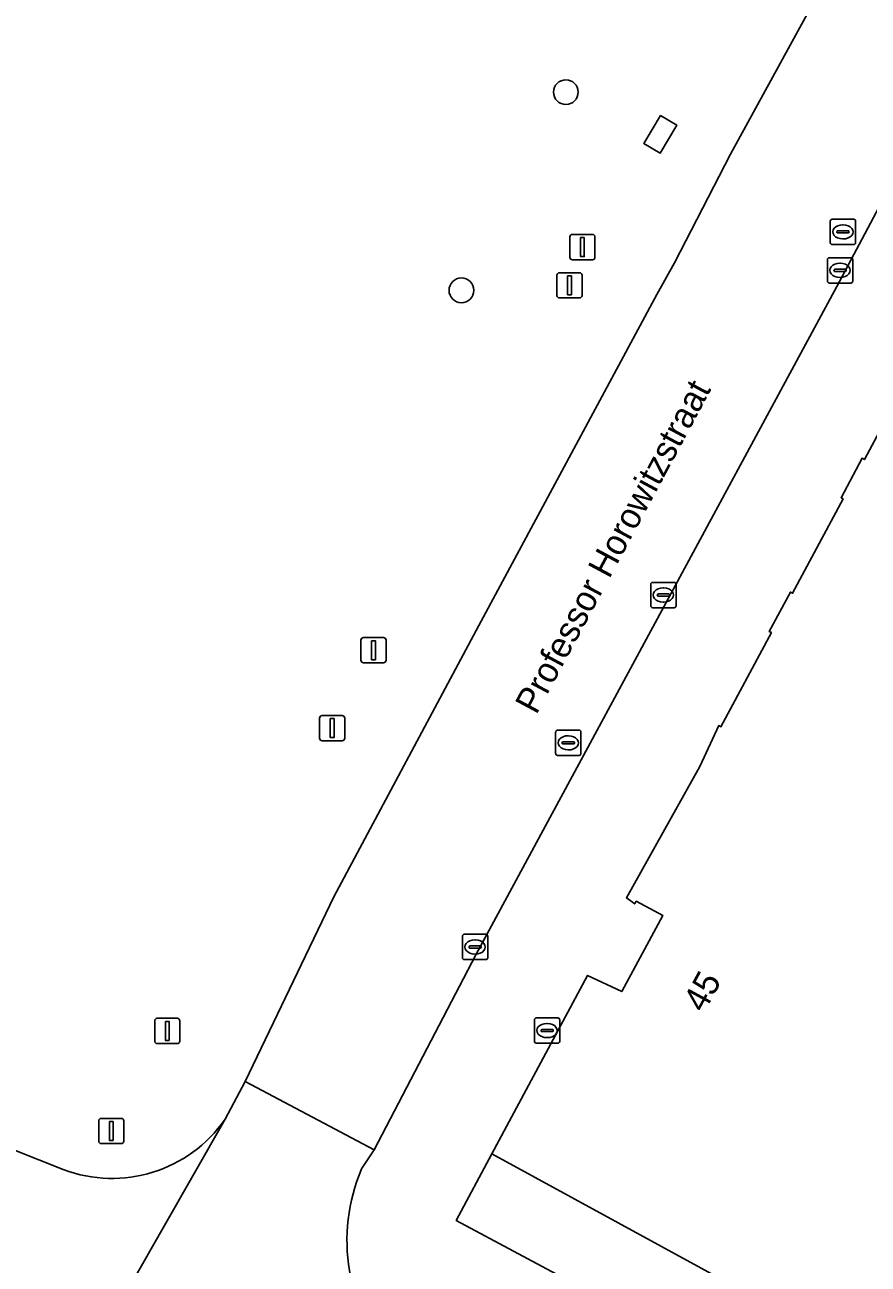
# Model space of a CAD drawing. Extents: x 159489 to 160304, y 383825 to 384531.
# Drawn here: x 159958.75 to 159992.1, y 384044.23 to 384093.22 of the extents above; entities that cross this region are included whole.
import ezdxf

# ---------------------------------------------------------------- set-up
doc = ezdxf.new("R2010")
doc.units = 0
for name, color, linetype in [('IMGEO_Boom', 7, 'Continuous'), ('IMGEO_Groenvoorziening', 7, 'Continuous'), ('IMGEO_Kolk', 7, 'Continuous'), ('IMGEO_Lichtmast', 7, 'Continuous'), ('IMGEO_Openbare_ruimte_label', 7, 'Continuous'), ('IMGEO_Pand', 7, 'Continuous'), ('IMGEO_Pand_nummerreeks', 7, 'Continuous'), ('IMGEO_Rijbaan_lokaal_gesloten', 7, 'Continuous'), ('IMGEO_Rioolput', 7, 'Continuous'), ('IMGEO_Terreindeel_open', 7, 'Continuous'), ('IMGEO_Voetpad_open', 7, 'Continuous')]:
    doc.layers.add(name, color=color, linetype=linetype)

msp = doc.modelspace()

# ---------------------------------------------------------------- linework, layer by layer
at = {"layer": 'IMGEO_Boom'}
for centre in [(159980.146, 384090.56), (159976.018, 384082.727)]:
    msp.add_circle(centre, 0.489, dxfattribs=at)
at = {"layer": 'IMGEO_Groenvoorziening'}
for points in [[(159941.364, 384123.56), (159925.758, 384094.623), (159925.487, 384093.814), (159920.135, 384063.9), (159960.274, 384047.972)], [(159966.672, 384049.958), (159967.463, 384051.458), (159970.972, 384058.755), (159976.703, 384069.478), (159983.744, 384082.565), (159984.446, 384083.814), (159986.651, 384088.113), (159991.605, 384097.15)]]:
    msp.add_lwpolyline(points, dxfattribs=at)
msp.add_lwpolyline([(159983.89, 384089.636), (159984.532, 384089.252), (159983.871, 384088.147), (159983.229, 384088.531)], close=True, dxfattribs=at)
msp.add_arc((159962.194, 384053.086), 5.462, 249.4231, 325.0666, dxfattribs=at)
at = {"layer": 'IMGEO_Kolk'}
for p, q in [((159990.489, 384083.089), (159990.489, 384083.941)), ((159990.564, 384084.015), (159991.416, 384084.015)), ((159991.49, 384083.941), (159991.49, 384083.089)), ((159990.748, 384083.509), (159990.748, 384083.521)), ((159991.186, 384083.472), (159990.788, 384083.472)), ((159990.791, 384083.558), (159991.189, 384083.558)), ((159990.977, 384083.795), (159991.002, 384083.795)), ((159991.232, 384083.521), (159991.232, 384083.509)), ((159991.416, 384083.015), (159990.564, 384083.015)), ((159991, 384083.235), (159990.975, 384083.235)), ((159983.579, 384071.182), (159984.431, 384071.182)), ((159983.504, 384070.256), (159983.504, 384071.108)), ((159983.763, 384070.676), (159983.763, 384070.688)), ((159983.806, 384070.725), (159984.204, 384070.725)), ((159983.992, 384070.962), (159984.017, 384070.962)), ((159984.247, 384070.688), (159984.247, 384070.676)), ((159984.505, 384071.108), (159984.505, 384070.256)), ((159984.431, 384070.182), (159983.579, 384070.182)), ((159984.201, 384070.639), (159983.803, 384070.639)), ((159984.015, 384070.402), (159983.99, 384070.402)), ((159976.058, 384056.345), (159976.058, 384057.197)), ((159976.133, 384057.271), (159976.985, 384057.271)), ((159976.546, 384057.051), (159976.571, 384057.051)), ((159977.059, 384057.197), (159977.059, 384056.345)), ((159976.317, 384056.765), (159976.317, 384056.777)), ((159976.755, 384056.728), (159976.357, 384056.728)), ((159976.36, 384056.814), (159976.758, 384056.814)), ((159976.569, 384056.491), (159976.544, 384056.491)), ((159976.801, 384056.777), (159976.801, 384056.765)), ((159976.985, 384056.271), (159976.133, 384056.271))]:
    msp.add_line(p, q, dxfattribs=at)
for points in [[(159990.489, 384083.089), (159990.489, 384083.941)], [(159990.564, 384084.015), (159991.416, 384084.015)], [(159991.49, 384083.941), (159991.49, 384083.089)], [(159991.416, 384083.015), (159990.564, 384083.015)], [(159983.579, 384071.182), (159984.431, 384071.182)], [(159983.504, 384070.256), (159983.504, 384071.108)], [(159984.505, 384071.108), (159984.505, 384070.256)], [(159984.431, 384070.182), (159983.579, 384070.182)], [(159976.058, 384056.345), (159976.058, 384057.197)], [(159976.133, 384057.271), (159976.985, 384057.271)], [(159977.059, 384057.197), (159977.059, 384056.345)], [(159976.985, 384056.271), (159976.133, 384056.271)]]:
    msp.add_lwpolyline(points, dxfattribs=at)
for centre, radius, start, end in [((159990.566, 384083.939), 0.0765, 91.552, 178.448), ((159990.566, 384083.939), 0.0765, 91.552, 178.448), ((159991.414, 384083.939), 0.0765, 1.552, 88.448), ((159991.414, 384083.939), 0.0765, 1.552, 88.448), ((159990.788, 384083.518), 0.0403, 85.8775, 175.7526), ((159990.785, 384083.508), 0.0366, 178.938, 274.7102), ((159991.189, 384083.515), 0.043, 264.8664, 352.4533), ((159991.193, 384083.52), 0.0386, 1.7309, 96.639), ((159990.566, 384083.091), 0.0765, 181.552, 268.448), ((159990.566, 384083.091), 0.0765, 181.552, 268.448), ((159991.414, 384083.091), 0.0765, 271.552, 358.448), ((159991.414, 384083.091), 0.0765, 271.552, 358.448), ((159983.581, 384071.106), 0.0765, 91.552, 178.448), ((159983.581, 384071.106), 0.0765, 91.552, 178.448), ((159984.429, 384071.106), 0.0765, 1.552, 88.448), ((159984.429, 384071.106), 0.0765, 1.552, 88.448), ((159983.803, 384070.685), 0.0403, 85.8775, 175.7526), ((159983.8, 384070.675), 0.0366, 178.938, 274.7102), ((159984.204, 384070.682), 0.043, 264.8664, 352.4533), ((159984.208, 384070.687), 0.0386, 1.7309, 96.639), ((159983.581, 384070.258), 0.0765, 181.552, 268.448), ((159983.581, 384070.258), 0.0765, 181.552, 268.448), ((159984.429, 384070.258), 0.0765, 271.552, 358.448), ((159984.429, 384070.258), 0.0765, 271.552, 358.448), ((159976.135, 384057.195), 0.0765, 91.552, 178.448), ((159976.135, 384057.195), 0.0765, 91.552, 178.448), ((159976.983, 384057.195), 0.0765, 1.552, 88.448), ((159976.983, 384057.195), 0.0765, 1.552, 88.448), ((159976.357, 384056.774), 0.0403, 85.8775, 175.7526), ((159976.354, 384056.764), 0.0366, 178.938, 274.7102), ((159976.758, 384056.771), 0.043, 264.8664, 352.4533), ((159976.762, 384056.776), 0.0386, 1.7309, 96.639), ((159976.135, 384056.347), 0.0765, 181.552, 268.448), ((159976.135, 384056.347), 0.0765, 181.552, 268.448), ((159976.983, 384056.347), 0.0765, 271.552, 358.448), ((159976.983, 384056.347), 0.0765, 271.552, 358.448)]:
    msp.add_arc(centre, radius, start, end, dxfattribs=at)
for centre, major_axis, ratio, start_param, end_param in [((159990.976, 384083.515), (-0.387, 0.002), 0.722429, 4.712389, 7.853982), ((159991.001, 384083.515), (-0.39, 0.002), 0.717154, 1.570796, 4.712389), ((159983.991, 384070.682), (-0.387, 0.002), 0.722429, 4.712389, 7.853982), ((159984.016, 384070.682), (-0.39, 0.002), 0.717154, 1.570796, 4.712389), ((159976.545, 384056.771), (-0.387, 0.002), 0.722429, 4.712389, 7.853982), ((159976.57, 384056.771), (-0.39, 0.002), 0.717154, 1.570796, 4.712389)]:
    msp.add_ellipse(centre, major_axis=major_axis, ratio=ratio, start_param=start_param, end_param=end_param, dxfattribs=at)
at = {"layer": 'IMGEO_Lichtmast'}
for p, q in [((159980.406, 384084.935), (159981.196, 384084.935)), ((159981.196, 384084.935), (159980.406, 384084.935)), ((159980.306, 384084.035), (159980.306, 384084.835)), ((159980.306, 384084.835), (159980.306, 384084.035)), ((159981.296, 384084.835), (159981.296, 384084.035)), ((159981.296, 384084.035), (159981.296, 384084.835)), ((159981.196, 384083.935), (159980.406, 384083.935)), ((159980.406, 384083.935), (159981.196, 384083.935)), ((159979.896, 384083.424), (159980.686, 384083.424)), ((159980.686, 384083.424), (159979.896, 384083.424)), ((159979.796, 384082.524), (159979.796, 384083.324)), ((159979.796, 384083.324), (159979.796, 384082.524)), ((159980.786, 384083.324), (159980.786, 384082.524)), ((159980.786, 384082.524), (159980.786, 384083.324)), ((159980.686, 384082.424), (159979.896, 384082.424)), ((159979.896, 384082.424), (159980.686, 384082.424)), ((159972.046, 384068.102), (159972.046, 384068.902)), ((159972.046, 384068.902), (159972.046, 384068.102)), ((159972.146, 384069.002), (159972.936, 384069.002)), ((159972.936, 384069.002), (159972.146, 384069.002)), ((159973.036, 384068.902), (159973.036, 384068.102)), ((159973.036, 384068.102), (159973.036, 384068.902)), ((159972.936, 384068.002), (159972.146, 384068.002)), ((159972.146, 384068.002), (159972.936, 384068.002)), ((159970.412, 384065.021), (159970.412, 384065.821)), ((159970.412, 384065.821), (159970.412, 384065.021)), ((159970.512, 384065.921), (159971.302, 384065.921)), ((159971.302, 384065.921), (159970.512, 384065.921)), ((159971.402, 384065.821), (159971.402, 384065.021)), ((159971.402, 384065.021), (159971.402, 384065.821)), ((159971.302, 384064.921), (159970.512, 384064.921)), ((159970.512, 384064.921), (159971.302, 384064.921)), ((159963.891, 384053.051), (159963.891, 384053.851)), ((159963.891, 384053.851), (159963.891, 384053.051)), ((159963.991, 384053.951), (159964.781, 384053.951)), ((159964.781, 384053.951), (159963.991, 384053.951)), ((159964.881, 384053.851), (159964.881, 384053.051)), ((159964.881, 384053.051), (159964.881, 384053.851)), ((159964.781, 384052.951), (159963.991, 384052.951)), ((159963.991, 384052.951), (159964.781, 384052.951)), ((159961.676, 384049.097), (159961.676, 384049.897)), ((159961.676, 384049.897), (159961.676, 384049.097)), ((159961.776, 384049.997), (159962.566, 384049.997)), ((159962.566, 384049.997), (159961.776, 384049.997)), ((159962.666, 384049.897), (159962.666, 384049.097)), ((159962.666, 384049.097), (159962.666, 384049.897)), ((159962.566, 384048.997), (159961.776, 384048.997)), ((159961.776, 384048.997), (159962.566, 384048.997))]:
    msp.add_line(p, q, dxfattribs=at)
for points in [[(159980.726, 384084.81), (159980.876, 384084.81), (159980.876, 384084.06), (159980.726, 384084.06), (159980.726, 384084.81)], [(159980.216, 384083.299), (159980.366, 384083.299), (159980.366, 384082.549), (159980.216, 384082.549), (159980.216, 384083.299)], [(159972.466, 384068.877), (159972.616, 384068.877), (159972.616, 384068.127), (159972.466, 384068.127), (159972.466, 384068.877)], [(159970.832, 384065.796), (159970.982, 384065.796), (159970.982, 384065.046), (159970.832, 384065.046), (159970.832, 384065.796)], [(159964.311, 384053.826), (159964.461, 384053.826), (159964.461, 384053.076), (159964.311, 384053.076), (159964.311, 384053.826)], [(159962.096, 384049.872), (159962.246, 384049.872), (159962.246, 384049.122), (159962.096, 384049.122), (159962.096, 384049.872)]]:
    msp.add_lwpolyline(points, dxfattribs=at)
for centre, start, end in [((159980.406, 384084.835), 90, 180), ((159980.406, 384084.835), 90, 180), ((159981.196, 384084.835), 0, 90), ((159981.196, 384084.835), 360, 90), ((159980.406, 384084.035), 180, 270), ((159980.406, 384084.035), 180, 270), ((159981.196, 384084.035), 270, 0), ((159981.196, 384084.035), 270, 0), ((159979.896, 384083.324), 90, 180), ((159979.896, 384083.324), 90, 180), ((159980.686, 384083.324), 0, 90), ((159980.686, 384083.324), 360, 90), ((159979.896, 384082.524), 180, 270), ((159979.896, 384082.524), 180, 270), ((159980.686, 384082.524), 270, 0), ((159980.686, 384082.524), 270, 0), ((159972.146, 384068.902), 90, 180), ((159972.146, 384068.902), 90, 180), ((159972.936, 384068.902), 0, 90), ((159972.936, 384068.902), 360, 90), ((159972.146, 384068.102), 180, 270), ((159972.146, 384068.102), 180, 270), ((159972.936, 384068.102), 270, 0), ((159972.936, 384068.102), 270, 0), ((159970.512, 384065.821), 90, 180), ((159970.512, 384065.821), 90, 180), ((159971.302, 384065.821), 0, 90), ((159971.302, 384065.821), 360, 90), ((159970.512, 384065.021), 180, 270), ((159970.512, 384065.021), 180, 270), ((159971.302, 384065.021), 270, 0), ((159971.302, 384065.021), 270, 0), ((159963.991, 384053.851), 90, 180), ((159963.991, 384053.851), 90, 180), ((159964.781, 384053.851), 0, 90), ((159964.781, 384053.851), 360, 90), ((159963.991, 384053.051), 180, 270), ((159963.991, 384053.051), 180, 270), ((159964.781, 384053.051), 270, 0), ((159964.781, 384053.051), 270, 0), ((159961.776, 384049.897), 90, 180), ((159961.776, 384049.897), 90, 180), ((159962.566, 384049.897), 0, 90), ((159962.566, 384049.897), 360, 90), ((159961.776, 384049.097), 180, 270), ((159961.776, 384049.097), 180, 270), ((159962.566, 384049.097), 270, 0), ((159962.566, 384049.097), 270, 0)]:
    msp.add_arc(centre, 0.1, start, end, dxfattribs=at)
at = {"layer": 'IMGEO_Pand'}
msp.add_lwpolyline([(159993.956, 384079.778), (159991.95, 384076.039), (159991.862, 384076.087), (159991.026, 384074.53), (159991.114, 384074.482), (159989.113, 384070.75), (159989.025, 384070.798), (159988.184, 384069.244), (159988.272, 384069.196), (159986.28, 384065.474), (159986.191, 384065.521), (159985.447, 384063.909), (159982.545, 384058.712), (159982.871, 384058.474), (159982.928, 384058.58), (159983.985, 384058.011), (159982.353, 384055.006), (159981.007, 384055.649), (159977.223, 384048.598), (159987.204, 384043.143), (159988.813, 384042.4), (159992.053, 384040.657), (159992.006, 384040.568), (159993.634, 384039.812)], dxfattribs=at)
at = {"layer": 'IMGEO_Rijbaan_lokaal_gesloten'}
for points in [[(159994.225, 384101.931), (159994.034, 384101.581), (159993.886, 384101.31), (159993.361, 384100.352), (159991.945, 384097.77), (159991.605, 384097.15), (159986.651, 384088.113), (159984.446, 384083.814), (159983.744, 384082.565), (159976.703, 384069.478), (159970.972, 384058.755), (159967.463, 384051.458), (159972.563, 384048.752), (159976.592, 384056.454), (159990.865, 384082.876)], [(159990.865, 384082.876), (159999.091, 384098.355), (159999.262, 384098.753)], [(159960.274, 384047.972), (159920.135, 384063.9)], [(159972.072, 384047.997), (159972.563, 384048.752), (159967.463, 384051.458), (159966.672, 384049.958), (159959.376, 384037.169)], [(159959.376, 384037.169), (159966.672, 384049.958)]]:
    msp.add_lwpolyline(points, dxfattribs=at)
for centre, radius, start, end in [((159962.194, 384053.086), 5.462, 249.4231, 325.0666), ((159978.703, 384045.162), 7.212, 156.8492, 222.0391)]:
    msp.add_arc(centre, radius, start, end, dxfattribs=at)
at = {"layer": 'IMGEO_Rioolput'}
for p, q in [((159990.601, 384084.612), (159990.601, 384085.464)), ((159990.676, 384085.538), (159991.528, 384085.538)), ((159991.602, 384085.464), (159991.602, 384084.612)), ((159990.86, 384085.032), (159990.86, 384085.044)), ((159991.298, 384084.995), (159990.9, 384084.995)), ((159990.903, 384085.081), (159991.301, 384085.081)), ((159991.089, 384085.318), (159991.114, 384085.318)), ((159991.344, 384085.044), (159991.344, 384085.032)), ((159991.528, 384084.538), (159990.676, 384084.538)), ((159991.112, 384084.758), (159991.087, 384084.758)), ((159979.743, 384064.414), (159979.743, 384065.266)), ((159979.818, 384065.34), (159980.67, 384065.34)), ((159980.744, 384065.266), (159980.744, 384064.414)), ((159980.002, 384064.834), (159980.002, 384064.846)), ((159980.44, 384064.797), (159980.042, 384064.797)), ((159980.045, 384064.883), (159980.443, 384064.883)), ((159980.231, 384065.12), (159980.256, 384065.12)), ((159980.486, 384064.846), (159980.486, 384064.834)), ((159980.67, 384064.34), (159979.818, 384064.34)), ((159980.254, 384064.56), (159980.229, 384064.56)), ((159978.905, 384053.042), (159978.905, 384053.894)), ((159978.98, 384053.968), (159979.832, 384053.968)), ((159979.207, 384053.511), (159979.605, 384053.511)), ((159979.393, 384053.748), (159979.418, 384053.748)), ((159979.906, 384053.894), (159979.906, 384053.042)), ((159979.164, 384053.462), (159979.164, 384053.474)), ((159979.602, 384053.425), (159979.204, 384053.425)), ((159979.416, 384053.188), (159979.391, 384053.188)), ((159979.648, 384053.474), (159979.648, 384053.462)), ((159979.832, 384052.968), (159978.98, 384052.968))]:
    msp.add_line(p, q, dxfattribs=at)
for points in [[(159990.601, 384084.612), (159990.601, 384085.464)], [(159990.676, 384085.538), (159991.528, 384085.538)], [(159991.602, 384085.464), (159991.602, 384084.612)], [(159991.528, 384084.538), (159990.676, 384084.538)], [(159979.743, 384064.414), (159979.743, 384065.266)], [(159979.818, 384065.34), (159980.67, 384065.34)], [(159980.744, 384065.266), (159980.744, 384064.414)], [(159980.67, 384064.34), (159979.818, 384064.34)], [(159978.905, 384053.042), (159978.905, 384053.894)], [(159978.98, 384053.968), (159979.832, 384053.968)], [(159979.906, 384053.894), (159979.906, 384053.042)], [(159979.832, 384052.968), (159978.98, 384052.968)]]:
    msp.add_lwpolyline(points, dxfattribs=at)
for centre, radius, start, end in [((159990.678, 384085.462), 0.0765, 91.552, 178.448), ((159990.678, 384085.462), 0.0765, 91.552, 178.448), ((159991.526, 384085.462), 0.0765, 1.552, 88.448), ((159991.526, 384085.462), 0.0765, 1.552, 88.448), ((159990.9, 384085.041), 0.0403, 85.8775, 175.7526), ((159990.897, 384085.031), 0.0366, 178.938, 274.7102), ((159991.301, 384085.038), 0.043, 264.8664, 352.4533), ((159991.305, 384085.043), 0.0386, 1.7309, 96.639), ((159990.678, 384084.614), 0.0765, 181.552, 268.448), ((159990.678, 384084.614), 0.0765, 181.552, 268.448), ((159991.526, 384084.614), 0.0765, 271.552, 358.448), ((159991.526, 384084.614), 0.0765, 271.552, 358.448), ((159979.82, 384065.264), 0.0765, 91.552, 178.448), ((159979.82, 384065.264), 0.0765, 91.552, 178.448), ((159980.668, 384065.264), 0.0765, 1.552, 88.448), ((159980.668, 384065.264), 0.0765, 1.552, 88.448), ((159980.042, 384064.843), 0.0403, 85.8775, 175.7526), ((159980.039, 384064.833), 0.0366, 178.938, 274.7102), ((159980.443, 384064.84), 0.043, 264.8664, 352.4533), ((159980.447, 384064.845), 0.0386, 1.7309, 96.639), ((159979.82, 384064.416), 0.0765, 181.552, 268.448), ((159979.82, 384064.416), 0.0765, 181.552, 268.448), ((159980.668, 384064.416), 0.0765, 271.552, 358.448), ((159980.668, 384064.416), 0.0765, 271.552, 358.448), ((159978.982, 384053.892), 0.0765, 91.552, 178.448), ((159978.982, 384053.892), 0.0765, 91.552, 178.448), ((159979.204, 384053.471), 0.0403, 85.8775, 175.7526), ((159979.609, 384053.473), 0.0386, 1.7309, 96.639), ((159979.83, 384053.892), 0.0765, 1.552, 88.448), ((159979.83, 384053.892), 0.0765, 1.552, 88.448), ((159978.982, 384053.044), 0.0765, 181.552, 268.448), ((159978.982, 384053.044), 0.0765, 181.552, 268.448), ((159979.201, 384053.461), 0.0366, 178.938, 274.7102), ((159979.605, 384053.468), 0.043, 264.8664, 352.4533), ((159979.83, 384053.044), 0.0765, 271.552, 358.448), ((159979.83, 384053.044), 0.0765, 271.552, 358.448)]:
    msp.add_arc(centre, radius, start, end, dxfattribs=at)
for centre, major_axis, ratio, start_param, end_param in [((159991.088, 384085.038), (-0.387, 0.002), 0.722429, 4.712389, 7.853982), ((159991.113, 384085.038), (-0.39, 0.002), 0.717154, 1.570796, 4.712389), ((159980.23, 384064.84), (-0.387, 0.002), 0.722429, 4.712389, 7.853982), ((159980.255, 384064.84), (-0.39, 0.002), 0.717154, 1.570796, 4.712389), ((159979.392, 384053.468), (-0.387, 0.002), 0.722429, 4.712389, 7.853982), ((159979.417, 384053.468), (-0.39, 0.002), 0.717154, 1.570796, 4.712389)]:
    msp.add_ellipse(centre, major_axis=major_axis, ratio=ratio, start_param=start_param, end_param=end_param, dxfattribs=at)
at = {"layer": 'IMGEO_Terreindeel_open'}
msp.add_lwpolyline([(159984.532, 384089.252), (159983.89, 384089.636), (159983.229, 384088.531), (159983.871, 384088.147)], close=True, dxfattribs=at)
at = {"layer": 'IMGEO_Voetpad_open'}
for points in [[(160001.237, 384097.592), (159999.262, 384098.753), (159999.091, 384098.355), (159990.865, 384082.876), (159976.592, 384056.454), (159972.563, 384048.752), (159972.072, 384047.997)], [(159997.515, 384034.347), (159975.813, 384045.96), (159977.223, 384048.598), (159981.007, 384055.649), (159982.353, 384055.006), (159983.985, 384058.011), (159982.928, 384058.58), (159982.871, 384058.474), (159982.545, 384058.712), (159985.447, 384063.909), (159986.191, 384065.521), (159986.28, 384065.474), (159988.272, 384069.196), (159988.184, 384069.244), (159989.025, 384070.798), (159989.113, 384070.75), (159991.114, 384074.482), (159991.026, 384074.53), (159991.862, 384076.087), (159991.95, 384076.039), (159993.956, 384079.778)]]:
    msp.add_lwpolyline(points, dxfattribs=at)
msp.add_lwpolyline([(159977.223, 384048.598), (159975.813, 384045.96), (159997.515, 384034.347), (159998.944, 384036.986), (159993.634, 384039.812), (159992.006, 384040.568), (159992.053, 384040.657), (159988.813, 384042.4), (159987.204, 384043.143)], close=True, dxfattribs=at)
msp.add_arc((159978.703, 384045.162), 7.212, 156.8492, 222.0391, dxfattribs=at)

# ---------------------------------------------------------------- texts
at = {"layer": 'IMGEO_Openbare_ruimte_label'}
msp.add_text('Professor Horowitzstraat', height=1, rotation=61.7691, dxfattribs=at).set_placement((159978.977, 384065.922))
at = {"layer": 'IMGEO_Pand_nummerreeks'}
msp.add_text('45', height=1, rotation=61.4956, dxfattribs=at).set_placement((159985.612, 384054.134))

doc.saveas('drawing.dxf')
